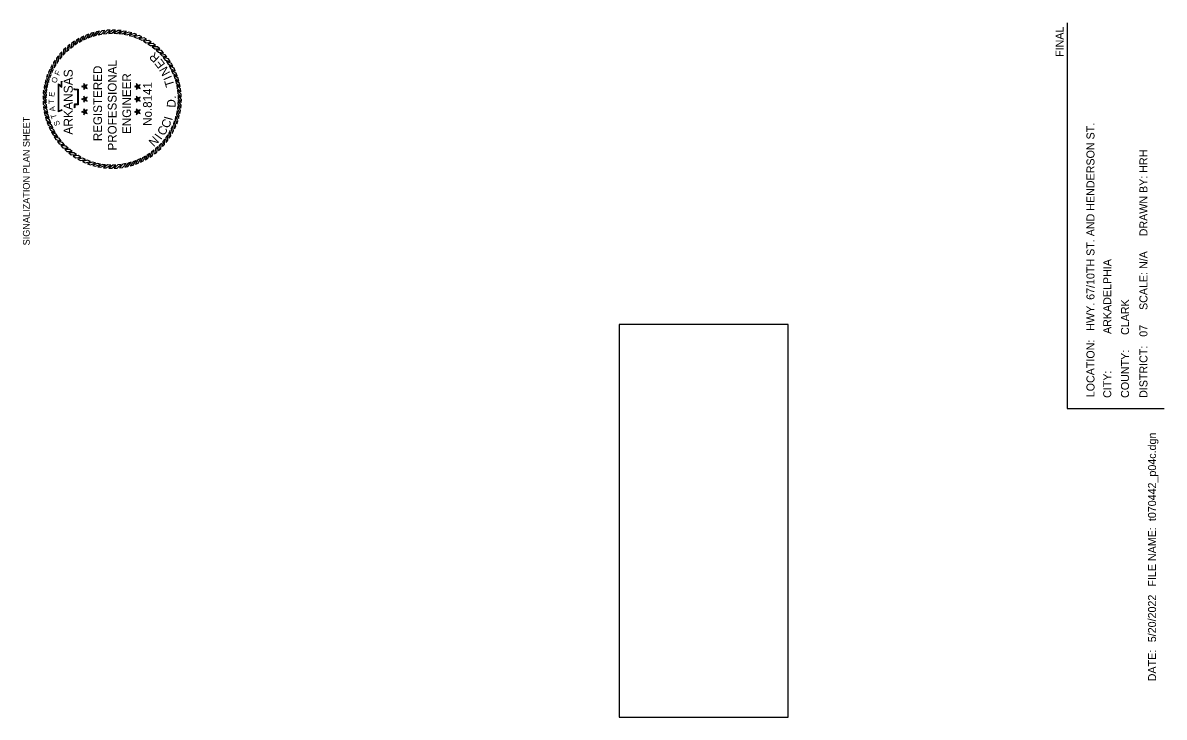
# Model space of a CAD drawing. Extents: x 610543 to 611161, y 419122 to 420064.
# Drawn here: x 610558 to 611161, y 419698 to 420064 of the extents above; entities that cross this region are included whole.
import ezdxf

# ---------------------------------------------------------------- set-up
doc = ezdxf.new("R2010")
doc.units = 0
for name, color, linetype in [('G-ANNO-SYMB', 7, 'Continuous'), ('G-ANNO-TEXT', 7, 'Continuous'), ('Level 10', 7, 'Continuous'), ('Level 57', 7, 'Continuous'), ('No Plot', 7, 'Continuous')]:
    doc.layers.add(name, color=color, linetype=linetype)

msp = doc.modelspace()

# ---------------------------------------------------------------- linework, layer by layer
at = {"layer": 'G-ANNO-SYMB'}
for points in [[(610593.3, 420058.21), (610591.83, 420057.65), (610590.45, 420055.22), (610592, 420055.92)], [(610596.03, 420059.07), (610594.52, 420058.62), (610592.96, 420056.31), (610594.55, 420056.88)], [(610598.82, 420059.71), (610597.29, 420059.38), (610595.54, 420057.2), (610597.18, 420057.64)], [(610601.65, 420060.12), (610600.1, 420059.92), (610598.19, 420057.88), (610599.86, 420058.2)], [(610604.51, 420060.32), (610602.94, 420060.24), (610600.88, 420058.35), (610602.57, 420058.54)], [(610607.37, 420060.29), (610605.81, 420060.33), (610603.6, 420058.61), (610605.3, 420058.66)], [(610610.23, 420060.03), (610608.67, 420060.2), (610606.34, 420058.66), (610608.03, 420058.58)], [(610613.05, 420059.55), (610611.51, 420059.84), (610609.06, 420058.49), (610610.75, 420058.28)], [(610615.83, 420058.86), (610614.31, 420059.26), (610611.77, 420058.11), (610613.43, 420057.76)], [(610618.54, 420057.94), (610617.07, 420058.47), (610614.44, 420057.51), (610616.07, 420057.04)], [(610621.18, 420056.82), (610619.75, 420057.46), (610617.05, 420056.71), (610618.64, 420056.11)], [(610583.28, 420052.74), (610582.06, 420051.76), (610581.5, 420049.02), (610582.75, 420050.16)], [(610585.61, 420054.4), (610584.32, 420053.51), (610583.55, 420050.83), (610584.89, 420051.87)], [(610588.07, 420055.87), (610586.71, 420055.09), (610585.73, 420052.47), (610587.15, 420053.4)], [(610590.64, 420057.14), (610589.22, 420056.47), (610588.04, 420053.94), (610589.52, 420054.75)], [(610623.71, 420055.49), (610622.34, 420056.24), (610619.59, 420055.71), (610621.13, 420054.99)], [(610626.14, 420053.97), (610624.83, 420054.82), (610622.05, 420054.51), (610623.52, 420053.67)], [(610628.44, 420052.26), (610627.2, 420053.22), (610624.4, 420053.12), (610625.81, 420052.17)], [(610630.6, 420050.38), (610629.43, 420051.43), (610626.64, 420051.55), (610627.96, 420050.49)], [(610577.15, 420046.74), (610576.19, 420045.5), (610576.29, 420042.71), (610577.24, 420044.11)], [(610579.03, 420048.9), (610577.98, 420047.74), (610577.86, 420044.95), (610578.92, 420046.27)], [(610581.08, 420050.9), (610579.94, 420049.83), (610579.6, 420047.05), (610580.76, 420048.29)], [(610632.6, 420048.33), (610631.52, 420049.47), (610628.75, 420049.81), (610629.98, 420048.65)], [(610634.44, 420046.13), (610633.45, 420047.35), (610630.71, 420047.91), (610631.85, 420046.66)], [(610636.1, 420043.8), (610635.21, 420045.09), (610632.52, 420045.86), (610633.56, 420044.52)], [(610572.59, 420039.48), (610571.95, 420038.05), (610572.7, 420035.36), (610573.3, 420036.94)], [(610573.92, 420042.02), (610573.17, 420040.64), (610573.7, 420037.9), (610574.42, 420039.43)], [(610575.44, 420044.44), (610574.59, 420043.13), (610574.9, 420040.35), (610575.74, 420041.83)], [(610637.57, 420041.34), (610636.79, 420042.7), (610634.17, 420043.68), (610635.1, 420042.26)], [(610638.84, 420038.77), (610638.17, 420040.19), (610635.63, 420041.37), (610636.45, 420039.89)], [(610570.56, 420034.13), (610570.15, 420032.62), (610571.31, 420030.07), (610571.65, 420031.73)], [(610571.47, 420036.85), (610570.94, 420035.37), (610571.9, 420032.74), (610572.37, 420034.37)], [(610639.91, 420036.12), (610639.35, 420037.58), (610636.91, 420038.96), (610637.61, 420037.41)], [(610640.76, 420033.38), (610640.32, 420034.89), (610638, 420036.45), (610638.58, 420034.86)], [(610641.4, 420030.59), (610641.08, 420032.13), (610638.89, 420033.87), (610639.34, 420032.23)], [(610569.38, 420028.53), (610569.21, 420026.97), (610570.75, 420024.64), (610570.83, 420026.33)], [(610569.86, 420031.36), (610569.57, 420029.81), (610570.92, 420027.37), (610571.14, 420029.05)], [(610591.03, 420030.53), (610590.51, 420030.9), (610589.36, 420030.53), (610590.51, 420030.15)], [(610591.03, 420030.53), (610591.23, 420031.13), (610590.51, 420032.11), (610590.51, 420030.9)], [(610591.03, 420030.53), (610590.51, 420030.15), (610590.51, 420028.94), (610591.23, 420029.92)], [(610591.03, 420030.53), (610591.67, 420030.53), (610592.38, 420031.51), (610591.23, 420031.13)], [(610591.03, 420030.53), (610591.23, 420029.92), (610592.38, 420029.55), (610591.67, 420030.53)], [(610618.96, 420030.53), (610618.44, 420030.9), (610617.29, 420030.53), (610618.44, 420030.15)], [(610618.96, 420030.53), (610619.16, 420031.13), (610618.44, 420032.11), (610618.44, 420030.9)], [(610618.96, 420030.53), (610618.44, 420030.15), (610618.44, 420028.94), (610619.16, 420029.92)], [(610618.96, 420030.53), (610619.6, 420030.53), (610620.31, 420031.51), (610619.16, 420031.13)], [(610618.96, 420030.53), (610619.16, 420029.92), (610620.31, 420029.55), (610619.6, 420030.53)], [(610641.82, 420027.76), (610641.62, 420029.31), (610639.57, 420031.22), (610639.89, 420029.56)], [(610642.01, 420024.9), (610641.94, 420026.47), (610640.05, 420028.53), (610640.23, 420026.84)], [(610569.12, 420025.68), (610569.08, 420024.11), (610570.8, 420021.91), (610570.75, 420023.6)], [(610569.09, 420022.81), (610569.17, 420021.25), (610571.06, 420019.19), (610570.87, 420020.87)], [(610591.03, 420023.86), (610590.51, 420024.23), (610589.36, 420023.86), (610590.51, 420023.48)], [(610591.03, 420023.86), (610591.23, 420024.46), (610590.51, 420025.44), (610590.51, 420024.23)], [(610591.03, 420023.86), (610590.51, 420023.48), (610590.51, 420022.27), (610591.23, 420023.25)], [(610591.03, 420023.86), (610591.67, 420023.86), (610592.38, 420024.84), (610591.23, 420024.46)], [(610591.03, 420023.86), (610591.23, 420023.25), (610592.38, 420022.88), (610591.67, 420023.86)], [(610618.96, 420023.86), (610618.44, 420024.23), (610617.29, 420023.86), (610618.44, 420023.48)], [(610618.96, 420023.86), (610619.16, 420024.46), (610618.44, 420025.44), (610618.44, 420024.23)], [(610618.96, 420023.86), (610618.44, 420023.48), (610618.44, 420022.27), (610619.16, 420023.25)], [(610618.96, 420023.86), (610619.6, 420023.86), (610620.31, 420024.84), (610619.16, 420024.46)], [(610618.96, 420023.86), (610619.16, 420023.25), (610620.31, 420022.88), (610619.6, 420023.86)], [(610641.73, 420019.18), (610641.9, 420020.74), (610640.35, 420023.07), (610640.27, 420021.38)], [(610641.98, 420022.04), (610642.03, 420023.6), (610640.31, 420025.81), (610640.36, 420024.11)], [(610569.29, 420019.96), (610569.49, 420018.4), (610571.53, 420016.5), (610571.22, 420018.16)], [(610569.71, 420017.12), (610570.03, 420015.59), (610572.22, 420013.85), (610571.77, 420015.48)], [(610591.03, 420017.19), (610590.51, 420017.56), (610589.36, 420017.19), (610590.51, 420016.81)], [(610591.03, 420017.19), (610591.23, 420017.79), (610590.51, 420018.77), (610590.51, 420017.56)], [(610591.03, 420017.19), (610590.51, 420016.81), (610590.51, 420015.6), (610591.23, 420016.58)], [(610591.03, 420017.19), (610591.67, 420017.19), (610592.38, 420018.17), (610591.23, 420017.79)], [(610591.03, 420017.19), (610591.23, 420016.58), (610592.38, 420016.21), (610591.67, 420017.19)], [(610618.96, 420017.19), (610618.44, 420017.56), (610617.29, 420017.19), (610618.44, 420016.81)], [(610618.96, 420017.19), (610619.16, 420017.79), (610618.44, 420018.77), (610618.44, 420017.56)], [(610618.96, 420017.19), (610618.44, 420016.81), (610618.44, 420015.6), (610619.16, 420016.58)], [(610618.96, 420017.19), (610619.6, 420017.19), (610620.31, 420018.17), (610619.16, 420017.79)], [(610618.96, 420017.19), (610619.16, 420016.58), (610620.31, 420016.21), (610619.6, 420017.19)], [(610640.55, 420013.58), (610640.96, 420015.1), (610639.8, 420017.64), (610639.46, 420015.98)], [(610641.25, 420016.36), (610641.54, 420017.9), (610640.18, 420020.35), (610639.97, 420018.67)], [(610570.34, 420014.33), (610570.79, 420012.83), (610573.1, 420011.26), (610572.53, 420012.86)], [(610571.2, 420011.6), (610571.76, 420010.13), (610574.19, 420008.76), (610573.49, 420010.3)], [(610637.19, 420005.7), (610637.94, 420007.07), (610637.4, 420009.82), (610636.68, 420008.28)], [(610638.51, 420008.23), (610639.15, 420009.67), (610638.41, 420012.36), (610637.81, 420010.77)], [(610639.64, 420010.87), (610640.16, 420012.35), (610639.21, 420014.97), (610638.74, 420013.34)], [(610572.27, 420008.94), (610572.94, 420007.52), (610575.47, 420006.34), (610574.66, 420007.83)], [(610573.54, 420006.38), (610574.32, 420005.02), (610576.94, 420004.04), (610576.01, 420005.45)], [(610575.01, 420003.92), (610575.9, 420002.62), (610578.58, 420001.85), (610577.54, 420003.19)], [(610633.95, 420000.97), (610634.91, 420002.21), (610634.82, 420005.01), (610633.86, 420003.61)], [(610635.66, 420003.27), (610636.52, 420004.58), (610636.2, 420007.36), (610635.36, 420005.89)], [(610576.67, 420001.58), (610577.65, 420000.36), (610580.39, 419999.8), (610579.25, 420001.06)], [(610578.51, 419999.39), (610579.58, 419998.25), (610582.36, 419997.9), (610581.12, 419999.06)], [(610580.51, 419997.34), (610581.67, 419996.29), (610584.47, 419996.16), (610583.14, 419997.22)], [(610627.83, 419994.97), (610629.05, 419995.96), (610629.61, 419998.7), (610628.35, 419997.56)], [(610630.03, 419996.81), (610631.17, 419997.89), (610631.51, 420000.66), (610630.35, 419999.43)], [(610632.07, 419998.81), (610633.12, 419999.98), (610633.25, 420002.77), (610632.19, 420001.45)], [(610582.67, 419995.46), (610583.91, 419994.5), (610586.7, 419994.6), (610585.3, 419995.55)], [(610584.97, 419993.75), (610586.28, 419992.89), (610589.06, 419993.21), (610587.58, 419994.05)], [(610587.39, 419992.23), (610588.77, 419991.47), (610591.51, 419992.01), (610589.98, 419992.73)], [(610589.93, 419990.9), (610591.36, 419990.26), (610594.06, 419991), (610592.47, 419991.6)], [(610615.08, 419988.65), (610616.58, 419989.09), (610618.15, 419991.41), (610616.55, 419990.83)], [(610617.81, 419989.5), (610619.28, 419990.06), (610620.65, 419992.5), (610619.11, 419991.8)], [(610620.47, 419990.57), (610621.89, 419991.24), (610623.07, 419993.78), (610621.58, 419992.96)], [(610623.03, 419991.84), (610624.39, 419992.63), (610625.37, 419995.24), (610623.96, 419994.31)], [(610625.49, 419993.31), (610626.79, 419994.2), (610627.56, 419996.89), (610626.22, 419995.85)], [(610592.56, 419989.77), (610594.04, 419989.25), (610596.67, 419990.2), (610595.04, 419990.68)], [(610595.28, 419988.86), (610596.79, 419988.45), (610599.34, 419989.61), (610597.68, 419989.95)], [(610598.06, 419988.16), (610599.6, 419987.87), (610602.04, 419989.23), (610600.36, 419989.44)], [(610600.88, 419987.68), (610602.44, 419987.52), (610604.77, 419989.06), (610603.08, 419989.14)], [(610603.73, 419987.43), (610605.3, 419987.38), (610607.5, 419989.1), (610605.81, 419989.05)], [(610606.6, 419987.4), (610608.16, 419987.48), (610610.22, 419989.36), (610608.54, 419989.18)], [(610609.45, 419987.59), (610611.01, 419987.79), (610612.92, 419989.84), (610611.25, 419989.52)], [(610612.29, 419988.01), (610613.82, 419988.33), (610615.56, 419990.52), (610613.93, 419990.07)]]:
    msp.add_lwpolyline(points, close=True, dxfattribs=at)
for points in [[(610579.08, 420018.01), (610577.24, 420017.16), (610577.23, 420031.88), (610578.77, 420030.65), (610578.76, 420031.65), (610578.75, 420032.48), (610578.84, 420033.32)], [(610578.98, 420018.23), (610577.47, 420017.53), (610577.46, 420031.39), (610579.01, 420030.16), (610578.99, 420031.65), (610578.98, 420032.47), (610579.07, 420033.29)], [(610585.06, 420029.41), (610585.32, 420029.1), (610585.71, 420028.99), (610586.5, 420028.91), (610587.3, 420028.91), (610587.3, 420021.16), (610586.16, 420021.16), (610585.68, 420021.16), (610585.52, 420020.63), (610585.52, 420019.55), (610585.31, 420019.41)], [(610585.25, 420029.56), (610585.45, 420029.31), (610585.75, 420029.22), (610586.52, 420029.14), (610587.53, 420029.14), (610587.53, 420020.93), (610586.16, 420020.93), (610585.86, 420020.93), (610585.75, 420020.59), (610585.75, 420019.43), (610585.44, 420019.22)]]:
    msp.add_lwpolyline(points, dxfattribs=at)
at = {"layer": 'Level 57'}
for points in [[(611109.39, 420064.17), (611109.39, 419860.59)], [(611109.39, 419860.59), (611160.6, 419860.59)]]:
    msp.add_lwpolyline(points, dxfattribs=at)
at = {"layer": 'No Plot'}
msp.add_lwpolyline([(610962.23, 419697.56), (610962.23, 419904.86), (610872.99, 419904.86), (610872.99, 419697.56)], close=True, dxfattribs=at)

# ---------------------------------------------------------------- texts
at = {"layer": 'G-ANNO-SYMB'}
for s, height, rotation, p in [('R', 4.59, 135.47796, (610630.95, 420045.95)), ('ARKANSAS', 4.737, 90, (610584.72, 420005.14)), ('REGISTERED', 4.585, 90, (610600.18, 420001.69)), ('PROFESSIONAL', 4.5855, 90, (610607.85, 419996.78)), ('E', 4.59, 127.64979, (610633.73, 420042.28)), ('N', 4.59, 118.7033, (610636.25, 420037.68)), ('O', 2.9, 71.2218, (610576.04, 420032.07)), ('F', 2.9, 65.36282, (610577.57, 420035.98)), ('ENGINEER', 4.585, 90, (610615.51, 420005.52)), ('I', 4.59, 114.23006, (610637.23, 420035.24)), ('T', 4.59, 106.77466, (610638.44, 420031.03)), ('E', 2.9, 86.67203, (610575.05, 420025.03)), ('No.8141', 4.567, 90, (610626.45, 420009.79)), ('T', 2.9, 91.47887, (610574.96, 420021.31)), ('D', 4.59, 86.64507, (610638.9, 420019.28)), ('.', 4.59, 94.84601, (610639.22, 420024.08)), ('A', 2.9, 98.67877, (610575.54, 420017.57)), ('T', 2.9, 106.90148, (610576.46, 420014.04)), ('S', 2.9, 109.77256, (610578.12, 420010.35)), ('C', 4.59, 58.68731, (610632.86, 420004.18)), ('C', 4.59, 66.51548, (610635.29, 420008.08)), ('I', 4.59, 74.34365, (610637.16, 420012.28)), ('N', 4.59, 45.26758, (610627.55, 419998.38)), ('I', 4.59, 54.21406, (610631.25, 420002.11))]:
    msp.add_text(s, height=height, rotation=rotation, dxfattribs=at).set_placement(p)
at = {"layer": 'G-ANNO-TEXT'}
msp.add_text('SIGNALIZATION PLAN SHEET', height=3.6, rotation=90, dxfattribs=at).set_placement((610562.05, 419946.66))
at = {"layer": 'Level 10'}
for s, p in [('FINAL', (611107.5, 420046.17)), ('LOCATION:   HWY. 67/10TH ST. AND HENDERSON ST.', (611123.82, 419866.48)), ('DISTRICT:   07     SCALE: N/A     DRAWN BY: HRH', (611151.77, 419866.13)), ('ARKADELPHIA ', (611132.67, 419899.9)), ('COUNTY:     CLARK', (611142.05, 419866.13)), ('CITY:       ', (611132.67, 419866.13)), ('t070442_p04c.dgn', (611156.31, 419801.06)), ('  FILE NAME: ', (611156.31, 419763.37)), ('5/20/2022', (611156.31, 419737.15)), ('DATE:  ', (611156.31, 419716.51))]:
    msp.add_text(s, height=4.221, rotation=90, dxfattribs=at).set_placement(p)

doc.saveas('drawing.dxf')
